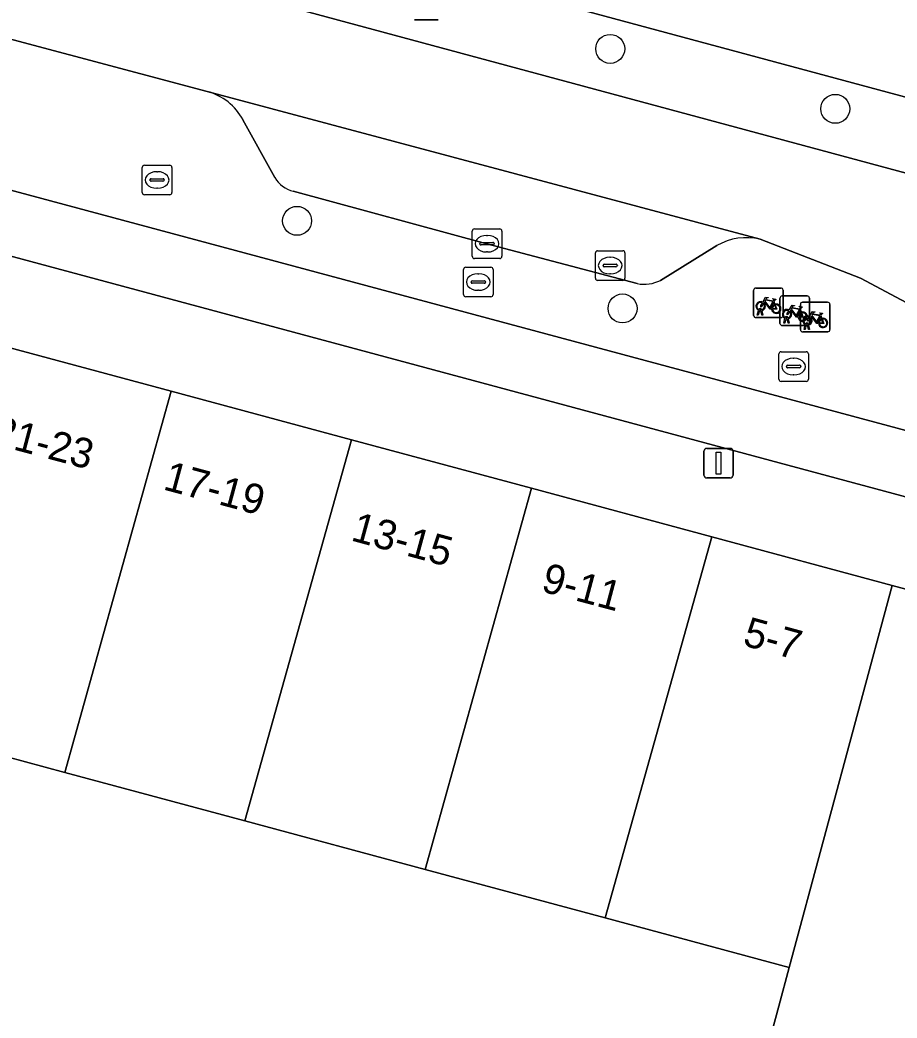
# Model space of a CAD drawing. Extents: x 160675 to 161153, y 383241 to 383714.
# Drawn here: x 160819.96 to 160849.57, y 383553.38 to 383587.08 of the extents above; entities that cross this region are included whole.
import ezdxf

# ---------------------------------------------------------------- set-up
doc = ezdxf.new("R2010")
doc.units = 0
for name, color, linetype in [('IMGEO_Berm_groen', 7, 'Continuous'), ('IMGEO_Berm_open', 7, 'Continuous'), ('IMGEO_Boom', 7, 'Continuous'), ('IMGEO_Erf', 7, 'Continuous'), ('IMGEO_Fietsenrek', 7, 'Continuous'), ('IMGEO_Fietspad_gesloten', 7, 'Continuous'), ('IMGEO_Kolk', 7, 'Continuous'), ('IMGEO_Lichtmast', 7, 'Continuous'), ('IMGEO_OVBaan_gesloten', 7, 'Continuous'), ('IMGEO_Pand', 7, 'Continuous'), ('IMGEO_Pand_nummerreeks', 7, 'Continuous'), ('IMGEO_Parkeervlak_open', 7, 'Continuous'), ('IMGEO_Rijbaan_lokaal_gesloten', 7, 'Continuous'), ('IMGEO_Rioolput', 7, 'Continuous'), ('IMGEO_Voetpad_open', 7, 'Continuous')]:
    doc.layers.add(name, color=color, linetype=linetype)

msp = doc.modelspace()

# ---------------------------------------------------------------- linework, layer by layer
at = {"layer": 'IMGEO_Berm_groen'}
msp.add_lwpolyline([(160870.684, 383578.867), (160797.835, 383598.49), (160797.171, 383596.125), (160869.874, 383576.512), (160913.282, 383564.496)], dxfattribs=at)
at = {"layer": 'IMGEO_Berm_open'}
for points in [[(160753.356, 383599.164), (160754.374, 383598.874), (160872.54, 383567.128), (160873.601, 383566.834), (160874.194, 383569.11), (160871.092, 383569.968), (160860.355, 383572.895)], [(160826.28, 383584.667), (160819.386, 383586.497)], [(160828.563, 383581.758), (160827.487, 383583.708)], [(160840.798, 383578.179), (160835.724, 383579.525), (160829.183, 383581.295)], [(160843.487, 383579.458), (160841.581, 383578.286)], [(160853.656, 383575.522), (160848.337, 383578.365), (160844.949, 383579.673)]]:
    msp.add_lwpolyline(points, dxfattribs=at)
for centre, radius, start, end in [((160825.752, 383582.763), 1.976, 28.5683, 74.4951), ((160829.416, 383582.254), 0.987, 210.1675, 256.3296), ((160844.481, 383577.775), 1.955, 76.1555, 120.5763), ((160841.039, 383579.333), 1.179, 258.2062, 297.3568)]:
    msp.add_arc(centre, radius, start, end, dxfattribs=at)
at = {"layer": 'IMGEO_Boom'}
for centre in [(160839.886, 383586.103), (160847.485, 383584.079), (160829.311, 383580.297), (160840.301, 383577.337)]:
    msp.add_circle(centre, 0.489, dxfattribs=at)
at = {"layer": 'IMGEO_Erf'}
msp.add_lwpolyline([(160813.434, 383552.307), (160835.666, 383546.367), (160835.773, 383546.777), (160835.675, 383546.802), (160837.272, 383552.948), (160839.91, 383552.262), (160844.825, 383550.984), (160845.578, 383553.78), (160845.929, 383555.083), (160839.72, 383556.755), (160833.637, 383558.393), (160827.553, 383560.031), (160821.47, 383561.669), (160819.477, 383562.206)], dxfattribs=at)
at = {"layer": 'IMGEO_Fietsenrek'}
for p, q in [((160844.725, 383577.102), (160844.725, 383577.943)), ((160844.725, 383577.943), (160844.725, 383577.102)), ((160844.8, 383578.027), (160845.641, 383578.027)), ((160845.641, 383578.027), (160844.8, 383578.027)), ((160845.69, 383577.76), (160846.531, 383577.76)), ((160846.531, 383577.76), (160845.69, 383577.76)), ((160845.725, 383577.952), (160845.725, 383577.111)), ((160845.725, 383577.111), (160845.725, 383577.952)), ((160845.412, 383577.576), (160845.448, 383577.481)), ((160845.615, 383576.835), (160845.615, 383577.676)), ((160845.615, 383577.676), (160845.615, 383576.835)), ((160846.305, 383576.623), (160846.305, 383577.464)), ((160846.305, 383577.464), (160846.305, 383576.623)), ((160846.38, 383577.548), (160847.221, 383577.548)), ((160847.221, 383577.548), (160846.38, 383577.548)), ((160846.615, 383577.685), (160846.615, 383576.844)), ((160846.615, 383576.844), (160846.615, 383577.685)), ((160847.305, 383577.473), (160847.305, 383576.632)), ((160847.305, 383576.632), (160847.305, 383577.473)), ((160844.852, 383577.111), (160844.891, 383577.271)), ((160844.886, 383577.111), (160844.852, 383577.111)), ((160844.921, 383577.259), (160844.886, 383577.111)), ((160844.963, 383577.283), (160844.962, 383577.287)), ((160845.004, 383577.111), (160844.97, 383577.253)), ((160844.994, 383577.294), (160844.995, 383577.287)), ((160845.002, 383577.257), (160845.037, 383577.111)), ((160845.037, 383577.111), (160845.004, 383577.111)), ((160846.302, 383577.309), (160846.338, 383577.214)), ((160846.992, 383577.097), (160847.028, 383577.002)), ((160845.65, 383577.027), (160844.809, 383577.027)), ((160844.809, 383577.027), (160845.65, 383577.027)), ((160846.54, 383576.76), (160845.699, 383576.76)), ((160845.699, 383576.76), (160846.54, 383576.76)), ((160845.742, 383576.844), (160845.781, 383577.004)), ((160845.776, 383576.844), (160845.742, 383576.844)), ((160845.811, 383576.992), (160845.776, 383576.844)), ((160845.853, 383577.016), (160845.852, 383577.02)), ((160845.894, 383576.844), (160845.86, 383576.986)), ((160845.884, 383577.027), (160845.885, 383577.02)), ((160845.892, 383576.99), (160845.927, 383576.844)), ((160845.927, 383576.844), (160845.894, 383576.844)), ((160846.432, 383576.632), (160846.471, 383576.792)), ((160846.501, 383576.78), (160846.466, 383576.632)), ((160846.543, 383576.804), (160846.542, 383576.808)), ((160846.584, 383576.632), (160846.55, 383576.774)), ((160846.574, 383576.815), (160846.575, 383576.808)), ((160846.582, 383576.778), (160846.617, 383576.632)), ((160847.23, 383576.548), (160846.389, 383576.548)), ((160846.389, 383576.548), (160847.23, 383576.548)), ((160846.466, 383576.632), (160846.432, 383576.632)), ((160846.617, 383576.632), (160846.584, 383576.632))]:
    msp.add_line(p, q, dxfattribs=at)
for points in [[(160845.059, 383577.501), (160845.007, 383577.411), (160844.967, 383577.386), (160844.968, 383577.433), (160845.023, 383577.527)], [(160845.038, 383577.553), (160845.133, 383577.717), (160845.219, 383577.703), (160845.221, 383577.694), (160845.165, 383577.683), (160845.138, 383577.638), (160845.394, 383577.597)], [(160845.334, 383577.309), (160845.284, 383577.309), (160845.093, 383577.56), (160845.074, 383577.528)], [(160845.381, 383577.572), (160845.124, 383577.613), (160845.107, 383577.584), (160845.274, 383577.364), (160845.381, 383577.572)], [(160845.429, 383577.474), (160845.399, 383577.551), (160845.29, 383577.333), (160845.333, 383577.333)], [(160845.363, 383577.333), (160845.483, 383577.332), (160845.439, 383577.446)], [(160845.459, 383577.453), (160845.514, 383577.308), (160845.364, 383577.308)], [(160845.394, 383577.597), (160845.419, 383577.646), (160845.413, 383577.65), (160845.39, 383577.654), (160845.378, 383577.661), (160845.377, 383577.664), (160845.379, 383577.669), (160845.474, 383577.654), (160845.476, 383577.644), (160845.466, 383577.631), (160845.454, 383577.625), (160845.44, 383577.631), (160845.412, 383577.576)], [(160845.928, 383577.286), (160846.023, 383577.45), (160846.109, 383577.436), (160846.111, 383577.427), (160846.055, 383577.416), (160846.028, 383577.371), (160846.284, 383577.33)], [(160845.949, 383577.234), (160845.897, 383577.144), (160845.857, 383577.119), (160845.858, 383577.166), (160845.913, 383577.26)], [(160846.224, 383577.042), (160846.174, 383577.042), (160845.983, 383577.293), (160845.964, 383577.261)], [(160846.271, 383577.305), (160846.014, 383577.346), (160845.997, 383577.317), (160846.164, 383577.097), (160846.271, 383577.305)], [(160846.319, 383577.207), (160846.289, 383577.284), (160846.18, 383577.066), (160846.223, 383577.066)], [(160846.253, 383577.066), (160846.373, 383577.065), (160846.329, 383577.179)], [(160846.349, 383577.186), (160846.404, 383577.041), (160846.254, 383577.041)], [(160846.284, 383577.33), (160846.309, 383577.379), (160846.303, 383577.383), (160846.28, 383577.387), (160846.268, 383577.394), (160846.267, 383577.397), (160846.269, 383577.402), (160846.364, 383577.387), (160846.366, 383577.377), (160846.356, 383577.364), (160846.344, 383577.358), (160846.33, 383577.364), (160846.302, 383577.309)], [(160846.618, 383577.074), (160846.713, 383577.238), (160846.799, 383577.224), (160846.801, 383577.215), (160846.745, 383577.204), (160846.718, 383577.159), (160846.974, 383577.118)], [(160846.914, 383576.83), (160846.864, 383576.83), (160846.673, 383577.081), (160846.654, 383577.049)], [(160846.961, 383577.093), (160846.704, 383577.134), (160846.687, 383577.105), (160846.854, 383576.885), (160846.961, 383577.093)], [(160847.009, 383576.995), (160846.979, 383577.072), (160846.87, 383576.854), (160846.913, 383576.854)], [(160846.974, 383577.118), (160846.999, 383577.167), (160846.993, 383577.171), (160846.97, 383577.175), (160846.958, 383577.182), (160846.957, 383577.185), (160846.959, 383577.19), (160847.054, 383577.175), (160847.056, 383577.165), (160847.046, 383577.152), (160847.034, 383577.146), (160847.02, 383577.152), (160846.992, 383577.097)], [(160846.639, 383577.022), (160846.587, 383576.932), (160846.547, 383576.907), (160846.548, 383576.954), (160846.603, 383577.048)], [(160846.943, 383576.854), (160847.063, 383576.853), (160847.019, 383576.967)], [(160847.039, 383576.974), (160847.094, 383576.829), (160846.944, 383576.829)]]:
    msp.add_lwpolyline(points, dxfattribs=at)
for centre, radius, start, end in [((160844.803, 383577.949), 0.0779, 92.4484, 184.2845), ((160844.803, 383577.949), 0.0779, 92.4484, 184.2845), ((160845.693, 383577.682), 0.0779, 92.4484, 184.2845), ((160845.693, 383577.682), 0.0779, 92.4484, 184.2845), ((160845.647, 383577.949), 0.0779, 2.4484, 94.2845), ((160845.647, 383577.949), 0.0779, 2.4484, 94.2845), ((160846.537, 383577.682), 0.0779, 2.4484, 94.2845), ((160846.537, 383577.682), 0.0779, 2.4484, 94.2845), ((160844.965, 383577.412), 0.159, 62.6766, 242.1369), ((160844.965, 383577.412), 0.129, 63.3192, 238.903), ((160844.965, 383577.412), 0.129, 283.6043, 43.4302), ((160844.965, 383577.412), 0.159, 283.5766, 46.6042), ((160845.492, 383577.328), 0.159, 113.3408, 178.3217), ((160845.492, 383577.328), 0.159, 187.0065, 105.7708), ((160845.492, 383577.328), 0.129, 113.923, 177.9556), ((160845.492, 383577.328), 0.129, 188.6715, 104.5883), ((160846.383, 383577.47), 0.0779, 92.4484, 184.2845), ((160846.383, 383577.47), 0.0779, 92.4484, 184.2845), ((160847.227, 383577.47), 0.0779, 2.4484, 94.2845), ((160847.227, 383577.47), 0.0779, 2.4484, 94.2845), ((160844.803, 383577.105), 0.0779, 182.4484, 274.2845), ((160844.803, 383577.105), 0.0779, 182.4484, 274.2845), ((160844.945, 383577.283), 0.0499, 12.8025, 158.6934), ((160844.965, 383577.412), 0.159, 253.9967, 271.7867), ((160844.945, 383577.283), 0.0174, 12.8025, 163.4502), ((160844.965, 383577.412), 0.129, 253.415, 269.0204), ((160845.647, 383577.105), 0.0779, 272.4484, 4.2845), ((160845.647, 383577.105), 0.0779, 272.4484, 4.2845), ((160845.855, 383577.145), 0.159, 62.6766, 242.1369), ((160845.855, 383577.145), 0.129, 63.3192, 238.903), ((160845.855, 383577.145), 0.129, 283.6043, 43.4302), ((160845.855, 383577.145), 0.159, 283.5766, 46.6042), ((160846.382, 383577.061), 0.159, 113.3408, 178.3217), ((160846.382, 383577.061), 0.159, 187.0065, 105.7708), ((160846.382, 383577.061), 0.129, 113.923, 177.9556), ((160846.382, 383577.061), 0.129, 188.6715, 104.5883), ((160846.545, 383576.933), 0.159, 62.6766, 242.1369), ((160845.693, 383576.838), 0.0779, 182.4484, 274.2845), ((160845.693, 383576.838), 0.0779, 182.4484, 274.2845), ((160845.835, 383577.016), 0.0499, 12.8025, 158.6934), ((160845.855, 383577.145), 0.159, 253.9967, 271.7867), ((160845.835, 383577.016), 0.0174, 12.8025, 163.4502), ((160845.855, 383577.145), 0.129, 253.415, 269.0204), ((160846.545, 383576.933), 0.129, 63.3192, 238.903), ((160846.525, 383576.804), 0.0499, 12.8025, 158.6934), ((160846.545, 383576.933), 0.159, 253.9967, 271.7867), ((160846.525, 383576.804), 0.0174, 12.8025, 163.4502), ((160846.545, 383576.933), 0.129, 253.415, 269.0204), ((160846.537, 383576.838), 0.0779, 272.4484, 4.2845), ((160846.537, 383576.838), 0.0779, 272.4484, 4.2845), ((160846.545, 383576.933), 0.129, 283.6043, 43.4302), ((160846.545, 383576.933), 0.159, 283.5766, 46.6042), ((160847.072, 383576.849), 0.159, 113.3408, 178.3217), ((160847.072, 383576.849), 0.159, 187.0065, 105.7708), ((160847.072, 383576.849), 0.129, 113.923, 177.9556), ((160847.072, 383576.849), 0.129, 188.6715, 104.5883), ((160846.383, 383576.626), 0.0779, 182.4484, 274.2845), ((160846.383, 383576.626), 0.0779, 182.4484, 274.2845), ((160847.227, 383576.626), 0.0779, 272.4484, 4.2845), ((160847.227, 383576.626), 0.0779, 272.4484, 4.2845)]:
    msp.add_arc(centre, radius, start, end, dxfattribs=at)
at = {"layer": 'IMGEO_Fietspad_gesloten'}
for points in [[(160741.54, 383600.127), (160851.652, 383570.489), (160869.912, 383565.633), (160904.417, 383556.04)], [(160904.814, 383558.169), (160877.012, 383565.887), (160875.567, 383566.288), (160873.601, 383566.834), (160872.54, 383567.128), (160754.374, 383598.874)]]:
    msp.add_lwpolyline(points, dxfattribs=at)
at = {"layer": 'IMGEO_Kolk'}
for p, q in [((160824.162, 383582.176), (160825.014, 383582.176)), ((160824.087, 383581.25), (160824.087, 383582.102)), ((160824.575, 383581.956), (160824.6, 383581.956)), ((160825.088, 383582.102), (160825.088, 383581.25)), ((160824.346, 383581.67), (160824.346, 383581.682)), ((160824.784, 383581.633), (160824.386, 383581.633)), ((160824.389, 383581.719), (160824.787, 383581.719)), ((160824.83, 383581.682), (160824.83, 383581.67)), ((160825.014, 383581.176), (160824.162, 383581.176)), ((160824.598, 383581.396), (160824.573, 383581.396)), ((160835.226, 383579.098), (160835.226, 383579.95)), ((160835.301, 383580.024), (160836.153, 383580.024)), ((160835.714, 383579.804), (160835.739, 383579.804)), ((160836.227, 383579.95), (160836.227, 383579.098)), ((160835.485, 383579.518), (160835.485, 383579.53)), ((160835.923, 383579.481), (160835.525, 383579.481)), ((160835.528, 383579.567), (160835.926, 383579.567)), ((160835.969, 383579.53), (160835.969, 383579.518)), ((160835.737, 383579.244), (160835.712, 383579.244)), ((160836.153, 383579.024), (160835.301, 383579.024)), ((160834.931, 383577.804), (160834.931, 383578.656)), ((160835.006, 383578.73), (160835.858, 383578.73)), ((160835.419, 383578.51), (160835.444, 383578.51)), ((160835.932, 383578.656), (160835.932, 383577.804)), ((160835.19, 383578.224), (160835.19, 383578.236)), ((160835.628, 383578.187), (160835.23, 383578.187)), ((160835.233, 383578.273), (160835.631, 383578.273)), ((160835.674, 383578.236), (160835.674, 383578.224)), ((160835.442, 383577.95), (160835.417, 383577.95)), ((160835.858, 383577.73), (160835.006, 383577.73)), ((160845.577, 383574.95), (160845.577, 383575.802)), ((160845.652, 383575.876), (160846.504, 383575.876)), ((160846.578, 383575.802), (160846.578, 383574.95)), ((160845.879, 383575.419), (160846.277, 383575.419)), ((160846.065, 383575.656), (160846.09, 383575.656)), ((160845.836, 383575.37), (160845.836, 383575.382)), ((160846.274, 383575.333), (160845.876, 383575.333)), ((160846.088, 383575.096), (160846.063, 383575.096)), ((160846.32, 383575.382), (160846.32, 383575.37)), ((160846.504, 383574.876), (160845.652, 383574.876))]:
    msp.add_line(p, q, dxfattribs=at)
for points in [[(160824.162, 383582.176), (160825.014, 383582.176)], [(160824.087, 383581.25), (160824.087, 383582.102)], [(160825.088, 383582.102), (160825.088, 383581.25)], [(160825.014, 383581.176), (160824.162, 383581.176)], [(160835.226, 383579.098), (160835.226, 383579.95)], [(160835.301, 383580.024), (160836.153, 383580.024)], [(160836.227, 383579.95), (160836.227, 383579.098)], [(160836.153, 383579.024), (160835.301, 383579.024)], [(160834.931, 383577.804), (160834.931, 383578.656)], [(160835.006, 383578.73), (160835.858, 383578.73)], [(160835.932, 383578.656), (160835.932, 383577.804)], [(160835.858, 383577.73), (160835.006, 383577.73)], [(160845.577, 383574.95), (160845.577, 383575.802)], [(160845.652, 383575.876), (160846.504, 383575.876)], [(160846.578, 383575.802), (160846.578, 383574.95)], [(160846.504, 383574.876), (160845.652, 383574.876)]]:
    msp.add_lwpolyline(points, dxfattribs=at)
for centre, radius, start, end in [((160824.164, 383582.1), 0.0765, 91.552, 178.448), ((160824.164, 383582.1), 0.0765, 91.552, 178.448), ((160825.012, 383582.1), 0.0765, 1.552, 88.448), ((160825.012, 383582.1), 0.0765, 1.552, 88.448), ((160824.386, 383581.679), 0.0403, 85.8775, 175.7526), ((160824.383, 383581.669), 0.0366, 178.938, 274.7102), ((160824.787, 383581.676), 0.043, 264.8664, 352.4533), ((160824.791, 383581.681), 0.0386, 1.7309, 96.639), ((160824.164, 383581.252), 0.0765, 181.552, 268.448), ((160824.164, 383581.252), 0.0765, 181.552, 268.448), ((160825.012, 383581.252), 0.0765, 271.552, 358.448), ((160825.012, 383581.252), 0.0765, 271.552, 358.448), ((160835.303, 383579.948), 0.0765, 91.552, 178.448), ((160835.303, 383579.948), 0.0765, 91.552, 178.448), ((160836.151, 383579.948), 0.0765, 1.552, 88.448), ((160836.151, 383579.948), 0.0765, 1.552, 88.448), ((160835.525, 383579.527), 0.0403, 85.8775, 175.7526), ((160835.522, 383579.517), 0.0366, 178.938, 274.7102), ((160835.926, 383579.524), 0.043, 264.8664, 352.4533), ((160835.93, 383579.529), 0.0386, 1.7309, 96.639), ((160835.303, 383579.1), 0.0765, 181.552, 268.448), ((160835.303, 383579.1), 0.0765, 181.552, 268.448), ((160836.151, 383579.1), 0.0765, 271.552, 358.448), ((160836.151, 383579.1), 0.0765, 271.552, 358.448), ((160835.008, 383578.654), 0.0765, 91.552, 178.448), ((160835.008, 383578.654), 0.0765, 91.552, 178.448), ((160835.856, 383578.654), 0.0765, 1.552, 88.448), ((160835.856, 383578.654), 0.0765, 1.552, 88.448), ((160835.23, 383578.233), 0.0403, 85.8775, 175.7526), ((160835.227, 383578.223), 0.0366, 178.938, 274.7102), ((160835.631, 383578.23), 0.043, 264.8664, 352.4533), ((160835.635, 383578.235), 0.0386, 1.7309, 96.639), ((160835.008, 383577.806), 0.0765, 181.552, 268.448), ((160835.008, 383577.806), 0.0765, 181.552, 268.448), ((160835.856, 383577.806), 0.0765, 271.552, 358.448), ((160835.856, 383577.806), 0.0765, 271.552, 358.448), ((160845.654, 383575.8), 0.0765, 91.552, 178.448), ((160845.654, 383575.8), 0.0765, 91.552, 178.448), ((160846.502, 383575.8), 0.0765, 1.552, 88.448), ((160846.502, 383575.8), 0.0765, 1.552, 88.448), ((160845.876, 383575.379), 0.0403, 85.8775, 175.7526), ((160846.281, 383575.381), 0.0386, 1.7309, 96.639), ((160845.873, 383575.369), 0.0366, 178.938, 274.7102), ((160846.277, 383575.376), 0.043, 264.8664, 352.4533), ((160845.654, 383574.952), 0.0765, 181.552, 268.448), ((160845.654, 383574.952), 0.0765, 181.552, 268.448), ((160846.502, 383574.952), 0.0765, 271.552, 358.448), ((160846.502, 383574.952), 0.0765, 271.552, 358.448)]:
    msp.add_arc(centre, radius, start, end, dxfattribs=at)
for centre, major_axis, ratio, start_param, end_param in [((160824.574, 383581.676), (-0.387, 0.002), 0.722429, 4.712389, 7.853982), ((160824.599, 383581.676), (-0.39, 0.002), 0.717154, 1.570796, 4.712389), ((160835.713, 383579.524), (-0.387, 0.002), 0.722429, 4.712389, 7.853982), ((160835.738, 383579.524), (-0.39, 0.002), 0.717154, 1.570796, 4.712389), ((160835.418, 383578.23), (-0.387, 0.002), 0.722429, 4.712389, 7.853982), ((160835.443, 383578.23), (-0.39, 0.002), 0.717154, 1.570796, 4.712389), ((160846.064, 383575.376), (-0.387, 0.002), 0.722429, 4.712389, 7.853982), ((160846.089, 383575.376), (-0.39, 0.002), 0.717154, 1.570796, 4.712389)]:
    msp.add_ellipse(centre, major_axis=major_axis, ratio=ratio, start_param=start_param, end_param=end_param, dxfattribs=at)
at = {"layer": 'IMGEO_Lichtmast'}
for p, q in [((160834.073, 383587.079), (160833.283, 383587.079)), ((160833.283, 383587.079), (160834.073, 383587.079)), ((160843.045, 383571.713), (160843.045, 383572.513)), ((160843.045, 383572.513), (160843.045, 383571.713)), ((160843.145, 383572.613), (160843.935, 383572.613)), ((160843.935, 383572.613), (160843.145, 383572.613)), ((160844.035, 383572.513), (160844.035, 383571.713)), ((160844.035, 383571.713), (160844.035, 383572.513)), ((160843.935, 383571.613), (160843.145, 383571.613)), ((160843.145, 383571.613), (160843.935, 383571.613))]:
    msp.add_line(p, q, dxfattribs=at)
msp.add_lwpolyline([(160843.465, 383572.488), (160843.615, 383572.488), (160843.615, 383571.738), (160843.465, 383571.738), (160843.465, 383572.488)], dxfattribs=at)
for centre, start, end in [((160843.145, 383572.513), 90, 180), ((160843.145, 383572.513), 90, 180), ((160843.935, 383572.513), 0, 90), ((160843.935, 383572.513), 360, 90), ((160843.145, 383571.713), 180, 270), ((160843.145, 383571.713), 180, 270), ((160843.935, 383571.713), 270, 0), ((160843.935, 383571.713), 270, 0)]:
    msp.add_arc(centre, 0.1, start, end, dxfattribs=at)
at = {"layer": 'IMGEO_OVBaan_gesloten'}
msp.add_lwpolyline([(160765.95, 383607.15), (160797.835, 383598.49), (160870.684, 383578.867), (160946.568, 383557.927)], dxfattribs=at)
at = {"layer": 'IMGEO_Pand'}
for points in [[(160819.477, 383562.206), (160821.47, 383561.669), (160825.065, 383574.542), (160818.982, 383576.181), (160815.386, 383563.308)], [(160831.149, 383572.903), (160825.065, 383574.542), (160821.47, 383561.669), (160827.553, 383560.031)], [(160831.149, 383572.903), (160827.553, 383560.031), (160833.637, 383558.393), (160837.232, 383571.265)], [(160839.72, 383556.755), (160843.316, 383569.626), (160837.232, 383571.265), (160833.637, 383558.393)], [(160839.72, 383556.755), (160845.929, 383555.083), (160849.404, 383567.986), (160843.316, 383569.626)], [(160857.143, 383564.601), (160857.461, 383565.816), (160849.404, 383567.986), (160845.929, 383555.083), (160845.578, 383553.78), (160844.825, 383550.984), (160843.174, 383544.853), (160849.994, 383543.081), (160850.028, 383543.072), (160850.324, 383542.913), (160852.917, 383548.465)]]:
    msp.add_lwpolyline(points, close=True, dxfattribs=at)
at = {"layer": 'IMGEO_Parkeervlak_open'}
for points in [[(160844.949, 383579.673), (160826.28, 383584.667)], [(160827.487, 383583.708), (160828.563, 383581.758)], [(160829.183, 383581.295), (160835.724, 383579.525), (160840.798, 383578.179)], [(160841.581, 383578.286), (160843.487, 383579.458)]]:
    msp.add_lwpolyline(points, dxfattribs=at)
for centre, radius, start, end in [((160825.752, 383582.763), 1.976, 28.5683, 74.4951), ((160829.416, 383582.254), 0.987, 210.1675, 256.3296), ((160844.481, 383577.775), 1.955, 76.1555, 120.5763), ((160841.039, 383579.333), 1.179, 258.2062, 297.3568)]:
    msp.add_arc(centre, radius, start, end, dxfattribs=at)
at = {"layer": 'IMGEO_Rijbaan_lokaal_gesloten'}
for points in [[(160748.774, 383605.431), (160752.694, 383604.486), (160754.68, 383603.938), (160760.442, 383602.399), (160762.407, 383601.874), (160786.733, 383595.326), (160792.524, 383593.731), (160819.386, 383586.497), (160826.28, 383584.667), (160844.949, 383579.673), (160848.337, 383578.365), (160853.656, 383575.522)], [(160869.874, 383576.512), (160797.171, 383596.125), (160768.531, 383603.87)]]:
    msp.add_lwpolyline(points, dxfattribs=at)
at = {"layer": 'IMGEO_Rioolput'}
for p, q in [((160839.383, 383578.36), (160839.383, 383579.212)), ((160839.458, 383579.286), (160840.31, 383579.286)), ((160840.384, 383579.212), (160840.384, 383578.36)), ((160839.642, 383578.78), (160839.642, 383578.792)), ((160839.685, 383578.829), (160840.083, 383578.829)), ((160839.871, 383579.066), (160839.896, 383579.066)), ((160840.126, 383578.792), (160840.126, 383578.78)), ((160840.08, 383578.743), (160839.682, 383578.743)), ((160839.894, 383578.506), (160839.869, 383578.506)), ((160840.31, 383578.286), (160839.458, 383578.286))]:
    msp.add_line(p, q, dxfattribs=at)
for points in [[(160839.383, 383578.36), (160839.383, 383579.212)], [(160839.458, 383579.286), (160840.31, 383579.286)], [(160840.384, 383579.212), (160840.384, 383578.36)], [(160840.31, 383578.286), (160839.458, 383578.286)]]:
    msp.add_lwpolyline(points, dxfattribs=at)
for centre, radius, start, end in [((160839.46, 383579.21), 0.0765, 91.552, 178.448), ((160839.46, 383579.21), 0.0765, 91.552, 178.448), ((160840.308, 383579.21), 0.0765, 1.552, 88.448), ((160840.308, 383579.21), 0.0765, 1.552, 88.448), ((160839.682, 383578.789), 0.0403, 85.8775, 175.7526), ((160839.679, 383578.779), 0.0366, 178.938, 274.7102), ((160840.083, 383578.786), 0.043, 264.8664, 352.4533), ((160840.087, 383578.791), 0.0386, 1.7309, 96.639), ((160839.46, 383578.362), 0.0765, 181.552, 268.448), ((160839.46, 383578.362), 0.0765, 181.552, 268.448), ((160840.308, 383578.362), 0.0765, 271.552, 358.448), ((160840.308, 383578.362), 0.0765, 271.552, 358.448)]:
    msp.add_arc(centre, radius, start, end, dxfattribs=at)
for centre, major_axis, ratio, start_param, end_param in [((160839.87, 383578.786), (-0.387, 0.002), 0.722429, 4.712389, 7.853982), ((160839.895, 383578.786), (-0.39, 0.002), 0.717154, 1.570796, 4.712389)]:
    msp.add_ellipse(centre, major_axis=major_axis, ratio=ratio, start_param=start_param, end_param=end_param, dxfattribs=at)
at = {"layer": 'IMGEO_Voetpad_open'}
for points in [[(160851.652, 383570.489), (160741.54, 383600.127)], [(160818.982, 383576.181), (160825.065, 383574.542), (160831.149, 383572.903), (160837.232, 383571.265), (160843.316, 383569.626), (160849.404, 383567.986), (160857.461, 383565.816), (160860.38, 383564.733), (160864.165, 383563.744), (160868.559, 383562.537), (160871.974, 383562.641), (160891.519, 383557.192), (160898.038, 383555.497), (160905.919, 383553.429)]]:
    msp.add_lwpolyline(points, dxfattribs=at)

# ---------------------------------------------------------------- texts
at = {"layer": 'IMGEO_Pand_nummerreeks'}
for s, rotation, p in [('21-23', 345.1206, (160818.977, 383572.774)), ('17-19', 344.9315, (160824.756, 383571.233)), ('13-15', 344.7242, (160831.095, 383569.512)), ('9-11', 345.0686, (160837.515, 383567.795)), ('5-7', 344.6445, (160844.321, 383565.972))]:
    msp.add_text(s, height=1, rotation=rotation, dxfattribs=at).set_placement(p)

doc.saveas('drawing.dxf')
